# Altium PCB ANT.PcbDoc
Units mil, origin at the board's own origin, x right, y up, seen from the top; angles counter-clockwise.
Board outline 2390 x 665 mil, 2 copper layers (Top Layer, Bottom Layer); 3 components, 0 nets, 5 pads, 0 vias.
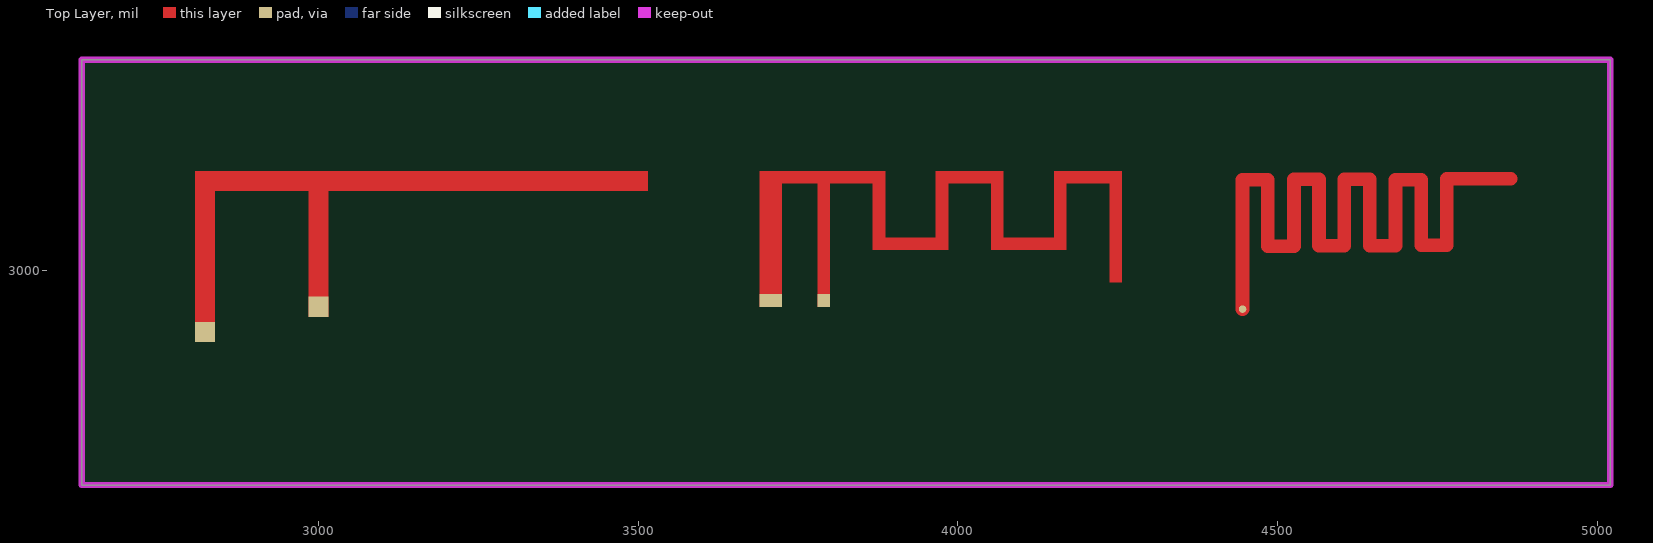
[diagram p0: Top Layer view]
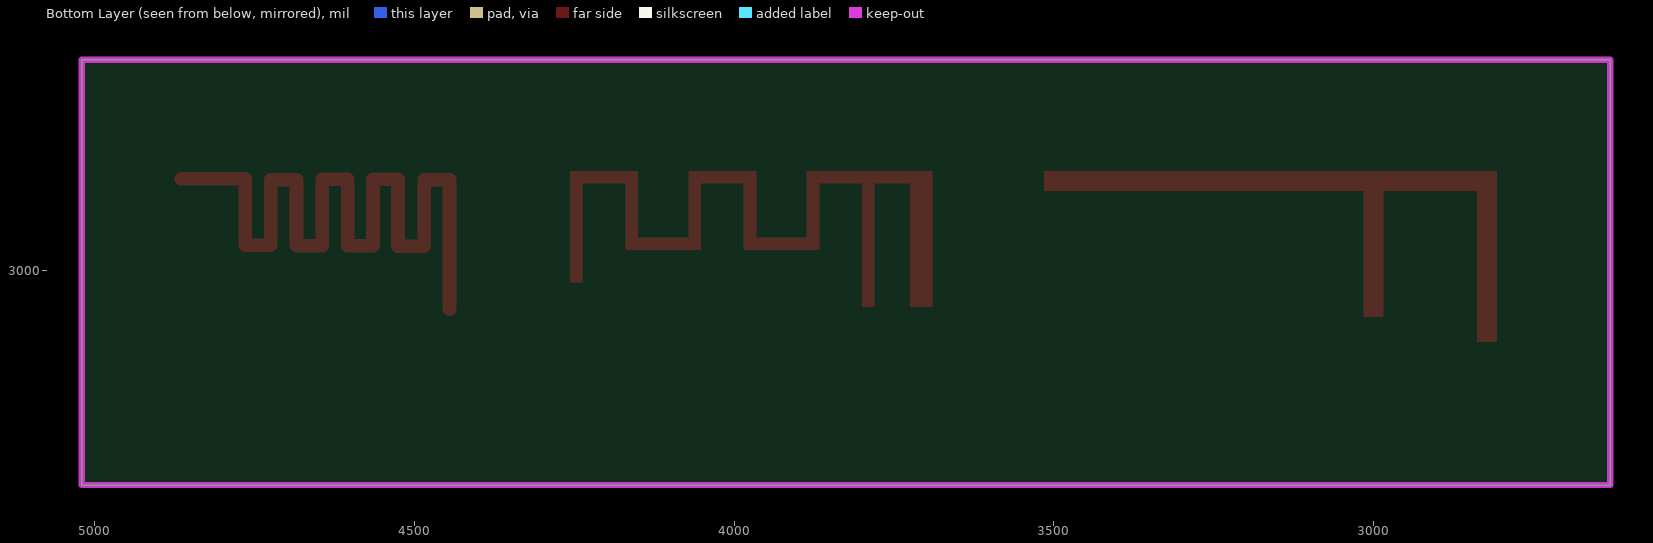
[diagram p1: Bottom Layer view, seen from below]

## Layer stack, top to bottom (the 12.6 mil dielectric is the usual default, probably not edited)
Top Solder: solder mask 0.4, Solder Resist, Dk 3.5
Top Layer: signal copper 1.4
Dielectric 1: dielectric 12.6, FR-4, Dk 4.8
Bottom Layer: signal copper 1.4
Bottom Solder: solder mask 0.4, Solder Resist, Dk 3.5

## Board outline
2630,2665 2630,3330 5020,3330 5020,2665

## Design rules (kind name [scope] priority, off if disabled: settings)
Clearance [All] p1: gap=10
PolygonConnect [All] p1: connectstyle=Relief reliefconductorwidth=10 reliefentries=4 polygonreliefangle="90 Angle" airgapwidth=10
RoutingVias [All] p1: holewidth=28 width=50 viastyle="Through Hole" minholewidth=28 minwidth=50 maxholewidth=28 maxwidth=50
SolderMaskExpansion [All] p1: expansion=4
Width [All] p1: maxlimit=10 minlimit=10 preferedwidth=10
30 further rules are at their usual default settings.

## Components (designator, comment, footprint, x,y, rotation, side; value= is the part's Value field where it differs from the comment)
? "" ANT-BTM 4784.07,3163.5 r180 top
? "" ANT-TI 3748.66,2957.43 r0 top
? "" ANT-F 3000,2943.65 r0 top

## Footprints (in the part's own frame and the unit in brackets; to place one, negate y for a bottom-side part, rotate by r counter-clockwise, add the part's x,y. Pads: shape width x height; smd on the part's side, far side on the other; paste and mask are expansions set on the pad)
ANT-BTM [mm]
  round 0.3 smd: 1(8.612,5.677)
  Top Layer lines w0.54: 8.612,5.677 8.612,0.544 7.607,0.544 7.607,3.179 6.57,3.179 6.57,0.523 5.575,0.523 5.575,3.158 4.57,3.158 4.57,0.512 3.554,0.512 3.554,3.158 2.538,3.158 2.538,0.544 1.521,0.544 1.521,3.137 0.495,3.137 0.495,0.502 -2.045,0.502
ANT-F [mm]
  rect 0.8x0.8 smd: 0(-4.5,-1) 1(0,0)
  Top Layer region: -4.9,-1.4 -4.1,-1.4 -4.1,5.4 -4.9,5.4
  Top Layer region: -0.4,-0.4 0.4,-0.4 0.4,5.4 -0.4,5.4
  Top Layer region: -4.9,4.6 13.1,4.6 13.1,5.4 -4.9,5.4
ANT-TI [mm]
  rect 0.9x0.5 smd: 0(-1.05,-0.1)
  rect 0.5x0.5 smd: 1(1.05,-0.1)
  Top Layer region: 7.7,1.91 10.7,1.91 10.7,2.41 7.7,2.41
  Top Layer region: 7.7,1.91 8.2,1.91 8.2,5.05 7.7,5.05
  Top Layer region: 5.5,4.55 8.2,4.55 8.2,5.05 5.5,5.05
  Top Layer region: 5.5,1.91 6,1.91 6,5.05 5.5,5.05
  Top Layer region: 3,1.91 6,1.91 6,2.41 3,2.41
  Top Layer region: 0.8,-0.35 1.3,-0.35 1.3,5.05 0.8,5.05
  Top Layer region: -1.5,4.55 3.5,4.55 3.5,5.05 -1.5,5.05
  Top Layer region: -1.5,-0.35 -0.6,-0.35 -0.6,5.05 -1.5,5.05
  Top Layer region: 3,1.91 3.5,1.91 3.5,5.05 3,5.05
  Top Layer region: 10.2,1.91 10.7,1.91 10.7,5.05 10.2,5.05
  Top Layer region: 10.2,4.55 12.9,4.55 12.9,5.05 10.2,5.05
  Top Layer region: 12.4,0.61 12.9,0.61 12.9,5.05 12.4,5.05

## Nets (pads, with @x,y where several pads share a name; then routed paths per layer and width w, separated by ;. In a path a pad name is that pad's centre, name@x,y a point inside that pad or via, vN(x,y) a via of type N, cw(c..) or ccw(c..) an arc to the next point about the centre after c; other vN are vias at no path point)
pads on no net: ?.0 ?.1

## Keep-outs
Keep-Out Layer:
  the board outline again, w10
